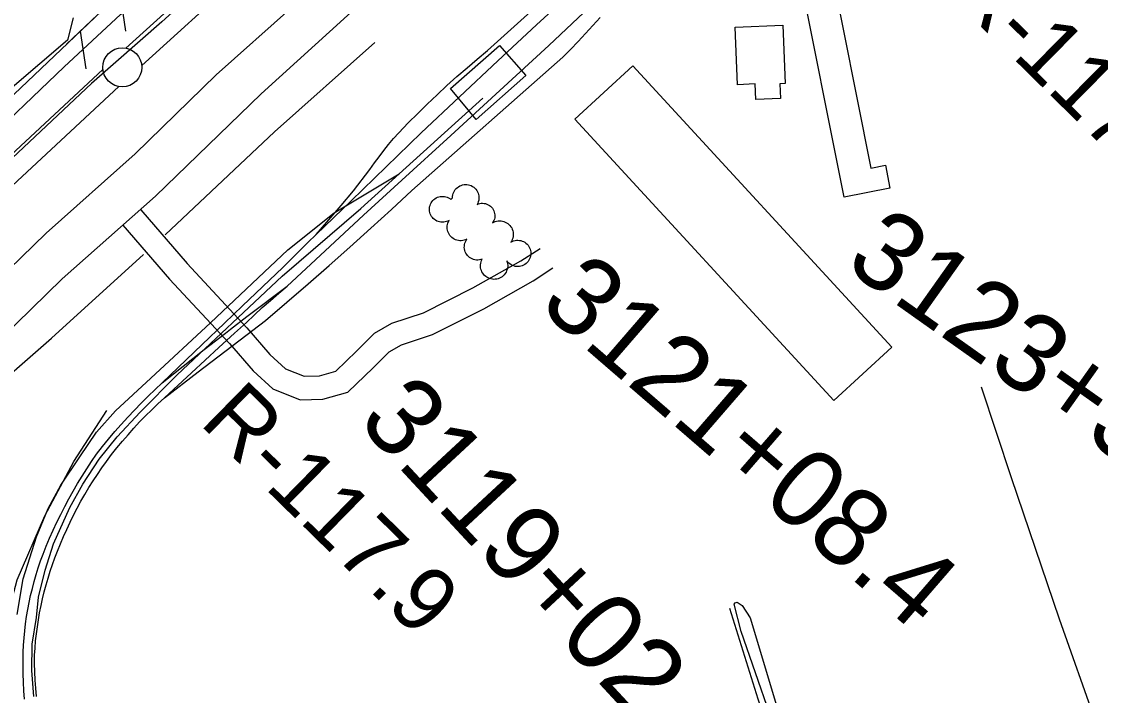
# Model space of a CAD drawing. Extents: x 3598634 to 3636690, y 517270 to 542944.
# Drawn here: x 3604442 to 3605821, y 523786 to 524647 of the extents above; entities that cross this region are included whole.
import ezdxf

# ---------------------------------------------------------------- set-up
doc = ezdxf.new("R2010")
doc.units = 0
for name, color, linetype in [('V-BLDG-OTLN', 7, 'Continuous'), ('V-FLOD-BASE', 7, 'Continuous'), ('V-LEVE-TOET', 7, 'Continuous'), ('V-RAIL-TRAK', 7, 'Continuous'), ('V-RIVR-RANG-IDEN', 7, 'Continuous'), ('V-ROAD-CNTR', 7, 'Continuous'), ('V-RRAP-FSHR', 7, 'Continuous'), ('V-SITE-STRC', 7, 'Continuous'), ('V-SITE-VEGE', 7, 'Continuous'), ('V-SURV-IDEN', 7, 'Continuous'), ('V-SURV-LINE', 7, 'Continuous'), ('V-TOPO-SHOR', 7, 'Continuous'), ('V-WETL-SWMP', 7, 'Continuous')]:
    doc.layers.add(name, color=color, linetype=linetype)

msp = doc.modelspace()

# ---------------------------------------------------------------- linework, layer by layer
at = {"layer": 'V-BLDG-OTLN'}
for points in [[(3605474.3, 524727.7), (3605527.6, 524459.8), (3605546.1, 524463.5), (3605551.9, 524434.3), (3605493.4, 524422.6), (3605434.4, 524719.8)], [(3605414.9, 524642.4), (3605418.1, 524568), (3605411.1, 524567.7), (3605412, 524548.7), (3605380.5, 524547.3), (3605379.6, 524567.4), (3605357.3, 524566.4), (3605354.2, 524639.8)], [(3605052.9, 524616.6), (3605086.9, 524578.1), (3605023.2, 524521.8), (3604990.6, 524561.6)]]:
    msp.add_lwpolyline(points, close=True, dxfattribs=at)
at = {"layer": 'V-FLOD-BASE'}
msp.add_lwpolyline([(3604597.4, 524678.5), (3604622.2, 524685.9), (3604645.8, 524685.3), (3604657.3, 524679.5), (3604621.6, 524646.7), (3604531.6, 524568), (3604423.6, 524466.3), (3604316.3, 524368.6), (3604187.1, 524251.3), (3604076.8, 524143.9), (3603970.7, 524046.7), (3603854.7, 523941), (3603732.9, 523828.3), (3603622.1, 523720.3), (3603505, 523601.9), (3603374.6, 523471.4), (3603267.8, 523366.8), (3603162.2, 523263.3), (3603049.1, 523148.3), (3602945.8, 523043.1), (3602849.3, 522944.8)], dxfattribs=at)
at = {"layer": 'V-LEVE-TOET'}
for points in [[(3605236.8, 525269.9), (3605163.4, 525206.1), (3605093.5, 525139.9), (3605012, 525069.7), (3604943.3, 525014.1), (3604875.7, 524958.4), (3604798.8, 524889.3), (3604715.5, 524807.5), (3604675.9, 524766.3), (3604667.2, 524772.1), (3604657.9, 524782.6), (3604637, 524793.1), (3604614.3, 524794.3), (3604586.4, 524783.9), (3604563.7, 524766), (3604562.5, 524747.3), (3604579.3, 524714.8), (3604589.7, 524682.2), (3604568.7, 524656), (3604497, 524589.3), (3604385.2, 524482.6)], [(3604362.1, 524268.6), (3604473.9, 524376.6), (3604587.5, 524478.1), (3604691.2, 524579.1), (3604788.5, 524666.1), (3604864.2, 524720), (3604919.5, 524769.9), (3604911.3, 524779), (3604903.9, 524787.4), (3604977.3, 524854.1), (3605078.6, 524942.3), (3605187, 525042.1), (3605263.8, 525108.2)]]:
    msp.add_lwpolyline(points, dxfattribs=at)
at = {"layer": 'V-RAIL-TRAK'}
for points in [[(3604622, 524185.3), (3604673.3, 524234.6), (3604701.8, 524261.8), (3604724.8, 524283.7), (3604776.4, 524332.7), (3604786.8, 524343.5), (3604797.4, 524354.2), (3604808.1, 524364.7), (3604818.9, 524375.1), (3604863.7, 524418.2), (3604908.4, 524461.6), (3604952.9, 524505.1), (3605001.9, 524551.1), (3605051.1, 524597), (3605100.4, 524642.8), (3605149.8, 524688.4), (3605162, 524698.5), (3605174.4, 524708.4), (3605186.9, 524718.1), (3605199.6, 524727.5), (3605212.5, 524736.8), (3605225.5, 524745.8)], [(3604818.9, 524375.1), (3604834.9, 524393.6), (3604850.8, 524412.2), (3604866.4, 524431), (3604887.4, 524458.2), (3604893.2, 524466.4), (3604899.1, 524474.4), (3604905.2, 524482.3), (3604911.4, 524490), (3604917.8, 524497.6), (3604924.4, 524505.1), (3604936.4, 524517.5), (3604948.5, 524529.6), (3604960.8, 524541.7), (3604973.3, 524553.5), (3604985.9, 524565.2), (3604998.7, 524576.7), (3605011.6, 524588), (3605024.7, 524599.2), (3605037.9, 524610.2), (3605097.4, 524663.6)], [(3604463.9, 523882.7), (3604465.5, 523891.7), (3604467.3, 523900.7), (3604469.2, 523909.6), (3604471.4, 523918.4), (3604473.7, 523927.3), (3604476.3, 523936), (3604479, 523944.7), (3604482, 523953.4), (3604485.1, 523961.9), (3604488.4, 523970.5), (3604492.1, 523979.8), (3604496.1, 523989.1), (3604500.1, 523998.2), (3604504.4, 524007.4), (3604508.9, 524016.4), (3604513.5, 524025.3), (3604518.3, 524034.1), (3604523.3, 524042.8), (3604528.5, 524051.5), (3604533.8, 524060), (3604539.3, 524068.4), (3604545, 524076.7), (3604550.9, 524084.9), (3604557.5, 524093.7), (3604564.3, 524102.3), (3604571.3, 524110.8), (3604578.4, 524119.2), (3604585.8, 524127.4), (3604593.3, 524135.5), (3604600.9, 524143.4), (3604608.8, 524151.1), (3604616.7, 524158.7), (3604624.9, 524166.1), (3604659.7, 524198.4), (3604694.6, 524230.5), (3604714.6, 524248.7), (3604729.7, 524262.5), (3604739.8, 524272), (3604750, 524281.5), (3604760.4, 524290.8), (3604770.9, 524299.9), (3604781.6, 524308.9), (3604830.3, 524354.3), (3604879.3, 524399.6), (3604928.4, 524444.6), (3604991, 524501.7), (3605053.6, 524559), (3605115.9, 524616.4), (3605160.9, 524658.6)], [(3604624.9, 524166.1), (3604667.9, 524199.3), (3604711, 524232.3), (3604721.8, 524240.6), (3604754.2, 524265.3), (3604781.4, 524288.5), (3604808.4, 524311.8), (3604835.3, 524335.3), (3604862, 524359), (3604888.5, 524382.9), (3604914.9, 524407), (3604941.1, 524431.2), (3605133.9, 524601.8), (3605143.8, 524611.6), (3605153.5, 524621.6), (3605163.1, 524631.7), (3605172.5, 524642), (3605181.7, 524652.5)], [(3604447.6, 523877.6), (3604448.9, 523886.7), (3604450.4, 523895.8), (3604452.1, 523904.8), (3604454, 523913.7), (3604456.2, 523922.7), (3604458.5, 523931.5), (3604461, 523940.4), (3604463.7, 523949.1), (3604466.7, 523957.8), (3604469.8, 523966.4), (3604474, 523976.8), (3604478.3, 523987.1), (3604482.9, 523997.3), (3604487.6, 524007.4), (3604492.5, 524017.4), (3604497.6, 524027.4), (3604502.8, 524037.2), (3604508.3, 524047), (3604513.9, 524056.7), (3604519.7, 524066.2), (3604525.7, 524075.7), (3604531.8, 524085), (3604538.1, 524094.2), (3604545.8, 524104), (3604553.6, 524113.6), (3604561.6, 524123.1), (3604569.7, 524132.4), (3604578, 524141.6), (3604586.5, 524150.7), (3604595.2, 524159.6), (3604604, 524168.3), (3604612.9, 524176.9), (3604622, 524185.3), (3604648.9, 524206.8), (3604675.9, 524228), (3604703.1, 524249.1), (3604709.4, 524254), (3604730.3, 524270), (3604781.6, 524308.9)], [(3604446.2, 523781.3), (3604445.4, 523792), (3604444.8, 523802.8), (3604444.5, 523813.5), (3604444.3, 523822.7), (3604444.3, 523831.9), (3604444.6, 523841.1), (3604445, 523850.2), (3604445.7, 523859.4), (3604446.5, 523868.5), (3604447.6, 523877.6)], [(3604461.4, 523784.5), (3604460.5, 523795.1), (3604459.8, 523805.6), (3604459.4, 523816.2), (3604459.1, 523826.8), (3604459.1, 523837.4), (3604459.7, 523846.5), (3604460.4, 523855.6), (3604461.4, 523864.6), (3604462.6, 523873.7), (3604463.9, 523882.7)]]:
    msp.add_lwpolyline(points, dxfattribs=at)
at = {"layer": 'V-ROAD-CNTR'}
for points in [[(3602956.2, 522834.4), (3603182.3, 523065.2), (3603319.9, 523214.6), (3603457.9, 523346.7), (3603601.9, 523495.1), (3603693.8, 523582.5), (3603771.1, 523651.5), (3603921, 523786.4), (3604091, 523940.4), (3604255.6, 524093.2), (3604395.8, 524222.3), (3604494.3, 524318.4), (3604613.7, 524423.8), (3604748.4, 524554.7), (3604904.9, 524696.9), (3605029.3, 524811.1), (3605245.7, 525003.3), (3605351.4, 525097.8), (3605421.2, 525164.8)], [(3604458.1, 523784.5), (3604455.5, 523817.8), (3604456.1, 523851.3), (3604461.6, 523885.6), (3604464.1, 523911.6), (3604472.4, 523946.1), (3604483.2, 523979.5), (3604503.9, 524026.1), (3604520.8, 524055.8), (3604541.4, 524087.7), (3604564.4, 524116.5), (3604594.1, 524148), (3604641.4, 524195.7), (3604775.2, 524321.6), (3604875.8, 524408.1), (3605031.6, 524549.3)], [(3604436.7, 523889.4), (3604444.6, 523935.1), (3604461.4, 523988.8), (3604476.5, 524024.7), (3604492.5, 524054.6), (3604517, 524090.8), (3604538.1, 524122.4), (3604562.5, 524149.8), (3604607.4, 524191.5), (3604683.6, 524262.3), (3604782.8, 524355.3), (3604841.6, 524402.7), (3604924.8, 524452.5)], [(3604594.6, 524406.7), (3604653.8, 524337.8), (3604730.3, 524255.9), (3604759.8, 524221.6), (3604779.7, 524203.4), (3604803.6, 524193.9), (3604823, 524194.6), (3604844, 524200.3), (3604870.5, 524225.8), (3604893.3, 524248.8), (3604915.4, 524261.8), (3604956, 524274.8), (3605018.8, 524306.7), (3605080.4, 524341.4), (3605104.8, 524357.3)], [(3604571.8, 524387.1), (3604631.5, 524317.8), (3604708, 524235.9), (3604738.2, 524200.7), (3604763.5, 524177.6), (3604798.4, 524163.8), (3604827.5, 524164.7), (3604859.3, 524173.4), (3604891.5, 524204.4), (3604911.9, 524224.9), (3604927.7, 524234.2), (3604967.4, 524247), (3605032.9, 524280.2), (3605096, 524315.7), (3605121.3, 524332.2)]]:
    msp.add_lwpolyline(points, dxfattribs=at)
at = {"layer": 'V-RRAP-FSHR'}
for p, q in [((3604567.9, 524683.1), (3604575.1, 524634.8)), ((3604517.1, 524634.9), (3604524.4, 524586.6))]:
    msp.add_line(p, q, dxfattribs=at)
for points in [[(3602908.1, 523078.8), (3602908.4, 523082.1), (3603162.2, 523342.2), (3603427.7, 523606.7), (3603682.1, 523863.6), (3603839.1, 523997.2), (3604065.9, 524207.2), (3604354.4, 524480.3), (3604579.6, 524694.2), (3604646.4, 524687.2)], [(3604499.7, 524618.3), (3604579.6, 524694.2), (3604646.4, 524687.2)]]:
    msp.add_lwpolyline(points, dxfattribs=at)
at = {"layer": 'V-SITE-STRC'}
msp.add_lwpolyline([(3605223.3, 524590.6), (3605554.3, 524231.2), (3605480.3, 524163), (3605149.2, 524522.4)], close=True, dxfattribs=at)
for points in [[(3605029.9, 524329), (3605029.3, 524330.8), (3605028.9, 524332.6), (3605028.8, 524334.5), (3605028.8, 524336.4), (3605029, 524338.2), (3605029.5, 524340.1), (3605030.1, 524341.8), (3605030.9, 524343.5), (3605029.2, 524343), (3605027.3, 524342.6), (3605025.5, 524342.4), (3605023.6, 524342.4), (3605021.7, 524342.7), (3605019.9, 524343.1), (3605018.2, 524343.8), (3605016.5, 524344.6), (3605014.9, 524345.6), (3605013.5, 524346.8), (3605012.2, 524348.2), (3605011.1, 524349.6), (3605010.1, 524351.2), (3605009.3, 524352.9), (3605008.7, 524354.7), (3605008.3, 524356.5), (3605008.1, 524358.4), (3605008.2, 524360.2), (3605008.4, 524362.1), (3605008.8, 524363.9), (3605009.5, 524365.7), (3605010.3, 524367.3), (3605011.3, 524368.9), (3605009.6, 524368.1), (3605007.9, 524367.6), (3605006.1, 524367.2), (3605004.2, 524367), (3605002.4, 524367), (3605000.5, 524367.2), (3604998.7, 524367.6), (3604996.9, 524368.2), (3604995.3, 524369), (3604993.7, 524369.9), (3604992.2, 524371.1), (3604990.9, 524372.4), (3604989.7, 524373.8), (3604988.6, 524375.3), (3604987.8, 524377), (3604987.1, 524378.7), (3604986.6, 524380.5), (3604986.3, 524382.3), (3604986.2, 524384.2), (3604986.3, 524386), (3604986.6, 524387.8), (3604987.1, 524389.6), (3604987.8, 524391.4), (3604988.6, 524393), (3604987, 524392.1), (3604985.4, 524391.5), (3604983.6, 524391), (3604981.8, 524390.7), (3604980, 524390.6), (3604978.2, 524390.7), (3604976.4, 524391), (3604974.6, 524391.5), (3604972.9, 524392.2), (3604971.3, 524393.1), (3604969.9, 524394.1), (3604968.5, 524395.3), (3604967.3, 524396.6), (3604966.2, 524398.1), (3604965.3, 524399.7), (3604964.5, 524401.4), (3604964, 524403.1), (3604963.7, 524404.9), (3604963.5, 524406.7), (3604963.6, 524408.5), (3604963.8, 524410.3), (3604964.3, 524412.1), (3604964.9, 524413.8), (3604965.7, 524415.4), (3604966.7, 524416.9), (3604967.9, 524418.3), (3604969.2, 524419.6), (3604970.6, 524420.7), (3604972.2, 524421.7), (3604973.8, 524422.5), (3604975.5, 524423), (3604977.3, 524423.4), (3604979.1, 524423.7), (3604980.9, 524423.7), (3604982.7, 524423.5), (3604984.5, 524423.1), (3604986.2, 524422.5), (3604987.9, 524421.7), (3604989.4, 524420.8), (3604990.9, 524419.6), (3604993.1, 524421.8), (3604993.2, 524423.7), (3604993.4, 524425.6), (3604993.9, 524427.4), (3604994.6, 524429.1)], [(3604994.6, 524429.1), (3604995.5, 524430.8), (3604996.6, 524432.3), (3604997.8, 524433.8), (3604999.2, 524435), (3605000.7, 524436.1), (3605002.4, 524437.1), (3605004.1, 524437.8), (3605005.9, 524438.4), (3605007.8, 524438.7), (3605009.6, 524438.9), (3605011.5, 524438.8), (3605013.4, 524438.5), (3605015.2, 524438), (3605017, 524437.4), (3605018.6, 524436.5), (3605020.2, 524435.4), (3605021.6, 524434.2), (3605022.9, 524432.8), (3605024, 524431.3), (3605025, 524429.7), (3605025.7, 524428), (3605026.3, 524426.2), (3605026.7, 524424.3), (3605026.8, 524422.5), (3605026.8, 524420.6), (3605026.5, 524418.7), (3605026, 524416.9), (3605025.4, 524415.1), (3605024.5, 524413.5), (3605026.2, 524414.1), (3605027.9, 524414.6), (3605029.7, 524414.9), (3605031.5, 524414.9), (3605033.4, 524414.8), (3605035.1, 524414.4), (3605036.9, 524413.9), (3605038.5, 524413.1), (3605040.1, 524412.2), (3605041.5, 524411.1), (3605042.8, 524409.9), (3605044, 524408.5), (3605045, 524407), (3605045.8, 524405.3), (3605046.4, 524403.6), (3605046.8, 524401.9), (3605047, 524400.1), (3605047.1, 524398.3), (3605046.9, 524396.5)], [(3605046.9, 524396.5), (3605046.5, 524394.7), (3605045.9, 524393), (3605045.1, 524391.4), (3605044.1, 524389.8), (3605045.8, 524390.7), (3605047.5, 524391.4), (3605049.3, 524392), (3605051.2, 524392.3), (3605053.1, 524392.4), (3605055, 524392.3), (3605056.8, 524392), (3605058.7, 524391.5), (3605060.4, 524390.9), (3605062.1, 524390), (3605063.7, 524388.9), (3605065.1, 524387.7), (3605066.4, 524386.4), (3605067.6, 524384.9), (3605068.6, 524383.3), (3605069.4, 524381.6), (3605070, 524379.8), (3605070.4, 524377.9), (3605070.6, 524376), (3605070.6, 524374.2), (3605070.4, 524372.3), (3605070, 524370.4), (3605069.4, 524368.6), (3605068.6, 524366.9), (3605067.7, 524365.3), (3605069.3, 524366.2), (3605071.1, 524366.8), (3605072.9, 524367.3), (3605074.7, 524367.6), (3605076.6, 524367.7), (3605078.4, 524367.5), (3605080.2, 524367.2), (3605082, 524366.6), (3605083.7, 524365.9), (3605085.4, 524365), (3605086.9, 524363.9), (3605088.2, 524362.6), (3605089.5, 524361.2), (3605090.5, 524359.7), (3605091.4, 524358.1), (3605092.1, 524356.4), (3605092.7, 524354.6), (3605093, 524352.8), (3605093.1, 524350.9), (3605093, 524349), (3605092.7, 524347.2), (3605092.2, 524345.4), (3605091.5, 524343.7), (3605090.6, 524342), (3605089.6, 524340.5), (3605088.3, 524339.1), (3605087, 524337.8), (3605085.5, 524336.7), (3605083.9, 524335.8), (3605082.2, 524335.1), (3605080.4, 524334.5), (3605078.6, 524334.2), (3605076.7, 524334), (3605074.8, 524334.1), (3605073, 524334.3), (3605071.2, 524334.8), (3605069.5, 524335.4), (3605067.8, 524336.3), (3605066.2, 524337.3), (3605064.8, 524338.5), (3605063.5, 524339.8), (3605062.4, 524341.3), (3605063, 524339.5), (3605063.3, 524337.6), (3605063.5, 524335.8), (3605063.5, 524333.9), (3605063.2, 524332), (3605062.8, 524330.2), (3605062.2, 524328.4), (3605061.4, 524326.7), (3605060.4, 524325.1), (3605059.2, 524323.6), (3605057.9, 524322.3), (3605056.4, 524321.1), (3605054.8, 524320.1), (3605053.2, 524319.2), (3605051.4, 524318.5), (3605049.6, 524318.1), (3605047.7, 524317.8), (3605045.8, 524317.7), (3605044, 524317.9), (3605042.1, 524318.2), (3605040.3, 524318.7), (3605038.6, 524319.5), (3605036.9, 524320.4), (3605035.4, 524321.5), (3605034, 524322.7), (3605032.7, 524324.1), (3605031.6, 524325.6), (3605030.6, 524327.2), (3605029.9, 524329)]]:
    msp.add_lwpolyline(points, dxfattribs=at)
at = {"layer": 'V-SITE-VEGE'}
msp.add_lwpolyline([(3605398.5, 523762), (3605361.7, 523867.8), (3605352.7, 523902.7), (3605354.3, 523904.3), (3605356.7, 523905), (3605363, 523901.1), (3605373.2, 523885.2), (3605409.6, 523764.7)], dxfattribs=at)
at = {"layer": 'V-SURV-LINE'}
for points in [[(3604575.8, 524613.1), (3604699, 524725)], [(3604719.2, 524702.8), (3604596, 524590.9)], [(3603736.9, 523832.9), (3604546.3, 524585.9)], [(3604566.7, 524564), (3603757.3, 523810.9)]]:
    msp.add_lwpolyline(points, dxfattribs=at)
msp.add_circle((3604571.1, 524588.6), 25, dxfattribs=at)
at = {"layer": 'V-TOPO-SHOR'}
for points in [[(3604626, 524374.7), (3604765.7, 524506.1), (3604893.8, 524620.3)], [(3603541.9, 523383.7), (3603649.6, 523493.9), (3603719.8, 523559.1), (3603792.3, 523624.4), (3603887.6, 523704.2), (3603985.3, 523787.5), (3604100, 523894.1), (3604265.5, 524046.3), (3604387.8, 524161.7), (3604480.8, 524242.7), (3604598, 524349.4)], [(3605668.5, 524180.3), (3605706.6, 524064.5), (3605768, 523883.8), (3605815.3, 523750.1), (3605864.7, 523599.4), (3605919.7, 523445), (3605972.7, 523290), (3606040.4, 523084.2), (3606052.2, 523050.6)], [(3605086.6, 522785.8), (3605005.2, 522764.8), (3604897.7, 522745.2), (3604795.6, 522714.4), (3604751.9, 522848.2), (3604714.2, 522965.1), (3604667.7, 523038.8), (3604635.7, 523099.5), (3604615.9, 523162.6), (3604578.2, 523277.8), (3604558.5, 523337.4), (3604526, 523446), (3604492.3, 523544.2), (3604450.5, 523678.6), (3604432, 523744.6), (3604422.7, 523798.4), (3604418.8, 523866.1), (3604437, 523933.8), (3604472.2, 524015.5), (3604509.1, 524084.9), (3604551.3, 524150.2)], [(3605347, 523897.5), (3605383, 523781.8), (3605457.8, 523558.1), (3605542.2, 523324.6)]]:
    msp.add_lwpolyline(points, dxfattribs=at)
at = {"layer": 'V-WETL-SWMP'}
msp.add_lwpolyline([(3604508.5, 524651.8), (3604501.3, 524623.2), (3604209, 524373.7)], dxfattribs=at)

# ---------------------------------------------------------------- texts
at = {"layer": 'V-RIVR-RANG-IDEN'}
for s, rotation, p in [('R-117.6', 315.4406, (3605623.3, 524684.5)), ('R-117.9', 315.5689, (3604668.2, 524133.6))]:
    msp.add_text(s, height=83, rotation=rotation, dxfattribs=at).set_placement(p)
at = {"layer": 'V-SURV-IDEN'}
for s, rotation, p in [('3123+36.1', 324.6682, (3605491.8, 524333.7)), ('3121+08.4', 319.1427, (3605101.2, 524282.1)), ('3119+02.0', 312.871, (3604869.9, 524135.5))]:
    msp.add_text(s, height=100, rotation=rotation, dxfattribs=at).set_placement(p)

doc.saveas('drawing.dxf')
